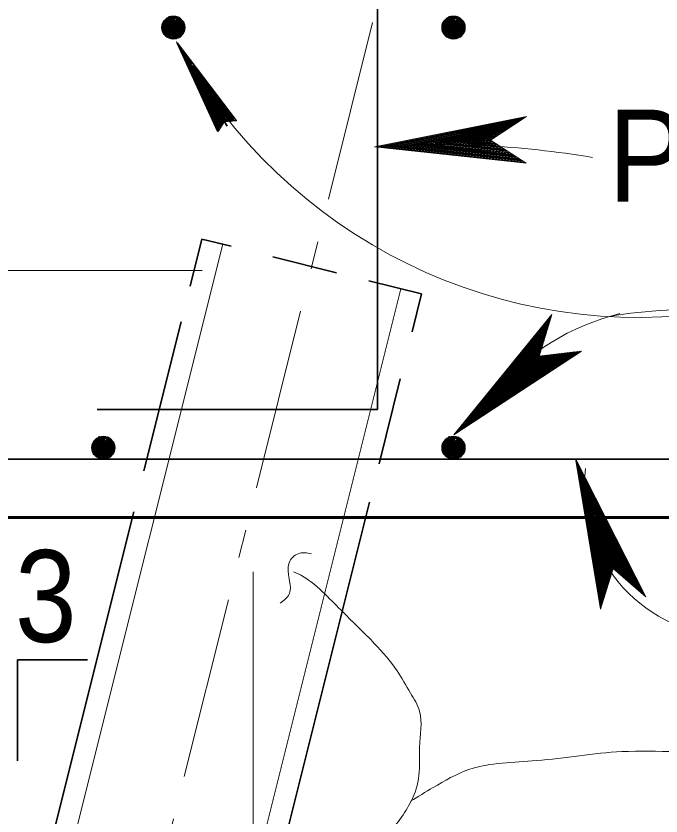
# Model space of a CAD drawing. Extents: x 144 to 252, y 360 to 425.
# Drawn here: x 191.264 to 193.567, y 410.769 to 413.625 of the extents above; entities that cross this region are included whole.
import ezdxf
from ezdxf.enums import TextEntityAlignment as Align

# ---------------------------------------------------------------- set-up
doc = ezdxf.new("R2010")
doc.units = 0
doc.header["$LTSCALE"] = 0.13
doc.linetypes.add('DOT_DASHED', pattern=[7.7, 5, -1.2, 0.3, -1.2])
for name, color, linetype, lineweight in [('1', 7, 'Continuous', 40), ('14', 7, 'Continuous', 13), ('16', 7, 'Continuous', 13), ('3', 7, 'Continuous', 13), ('4', 7, 'Continuous', 35), ('5', 7, 'Continuous', 35)]:
    doc.layers.add(name, color=color, linetype=linetype, lineweight=lineweight)

msp = doc.modelspace()

# ---------------------------------------------------------------- linework, layer by layer
at = {"layer": '1'}
for p, q in [((191.799, 413.6072), (191.7965, 413.5623)), ((191.7965, 413.5922), (191.8565, 413.5822)), ((191.7965, 413.5897), (191.8565, 413.5772)), ((191.8015, 413.6072), (191.799, 413.5623)), ((191.799, 413.6072), (191.859, 413.5972)), ((191.799, 413.6047), (191.859, 413.5947)), ((191.799, 413.6022), (191.859, 413.5897)), ((191.799, 413.5997), (191.859, 413.5872)), ((191.799, 413.5947), (191.8565, 413.5847)), ((191.8015, 413.6122), (191.859, 413.6022)), ((191.804, 413.6072), (191.8015, 413.5623)), ((191.8065, 413.6072), (191.804, 413.5623)), ((191.809, 413.6072), (191.8065, 413.5623)), ((191.814, 413.6072), (191.8115, 413.5623)), ((191.8165, 413.6072), (191.814, 413.5623)), ((191.819, 413.6072), (191.8165, 413.5623)), ((191.8215, 413.6072), (191.819, 413.5623)), ((191.824, 413.6072), (191.8215, 413.5623)), ((191.8265, 413.6072), (191.824, 413.5623)), ((191.829, 413.6072), (191.8265, 413.5623)), ((191.834, 413.6047), (191.829, 413.5598)), ((191.839, 413.6047), (191.834, 413.5598)), ((191.8415, 413.6047), (191.839, 413.5598)), ((191.8415, 413.6047), (191.839, 413.5598)), ((191.844, 413.6047), (191.8415, 413.5598)), ((191.8465, 413.6047), (191.844, 413.5598)), ((191.849, 413.6047), (191.8465, 413.5598)), ((191.8515, 413.6047), (191.849, 413.5598)), ((191.854, 413.6047), (191.8515, 413.5598)), ((191.8565, 413.6047), (191.854, 413.5598)), ((191.8615, 413.6047), (191.859, 413.5598)), ((192.799, 413.6072), (192.7965, 413.5623)), ((192.7965, 413.5922), (192.8565, 413.5822)), ((192.7965, 413.5897), (192.8565, 413.5772)), ((192.8015, 413.6072), (192.799, 413.5623)), ((192.799, 413.6072), (192.859, 413.5972)), ((192.799, 413.6047), (192.859, 413.5947)), ((192.799, 413.6022), (192.859, 413.5897)), ((192.799, 413.5997), (192.859, 413.5872)), ((192.799, 413.5947), (192.8565, 413.5847)), ((192.8015, 413.6122), (192.859, 413.6022)), ((192.804, 413.6072), (192.8015, 413.5623)), ((192.8065, 413.6072), (192.804, 413.5623)), ((192.809, 413.6072), (192.8065, 413.5623)), ((192.814, 413.6072), (192.8115, 413.5623)), ((192.8165, 413.6072), (192.814, 413.5623)), ((192.819, 413.6072), (192.8165, 413.5623)), ((192.8215, 413.6072), (192.819, 413.5623)), ((192.824, 413.6072), (192.8215, 413.5623)), ((192.8265, 413.6072), (192.824, 413.5623)), ((192.829, 413.6072), (192.8265, 413.5623)), ((192.834, 413.6047), (192.829, 413.5598)), ((192.839, 413.6047), (192.834, 413.5598)), ((192.8415, 413.6047), (192.839, 413.5598)), ((192.8415, 413.6047), (192.839, 413.5598)), ((192.844, 413.6047), (192.8415, 413.5598)), ((192.8465, 413.6047), (192.844, 413.5598)), ((192.849, 413.6047), (192.8465, 413.5598)), ((192.8515, 413.6047), (192.849, 413.5598)), ((192.854, 413.6047), (192.8515, 413.5598)), ((192.8565, 413.6047), (192.854, 413.5598)), ((192.8615, 413.6047), (192.859, 413.5598)), ((191.7915, 413.5648), (191.8515, 413.5548)), ((191.794, 413.5797), (191.854, 413.5673)), ((191.794, 413.5722), (191.854, 413.5623)), ((191.794, 413.5697), (191.8515, 413.5598)), ((191.794, 413.5673), (191.8515, 413.5573)), ((191.7965, 413.5872), (191.854, 413.5747)), ((191.7965, 413.5847), (191.854, 413.5722)), ((192.7915, 413.5648), (192.8515, 413.5548)), ((192.794, 413.5797), (192.854, 413.5673)), ((192.794, 413.5722), (192.854, 413.5623)), ((192.794, 413.5697), (192.8515, 413.5598)), ((192.794, 413.5673), (192.8515, 413.5573)), ((192.7965, 413.5872), (192.854, 413.5747)), ((192.7965, 413.5847), (192.854, 413.5722)), ((191.549, 412.1072), (191.5465, 412.0623)), ((191.5515, 412.1072), (191.549, 412.0623)), ((191.549, 412.1072), (191.609, 412.0972)), ((191.549, 412.1047), (191.609, 412.0947)), ((191.5515, 412.1122), (191.609, 412.1022)), ((191.554, 412.1072), (191.5515, 412.0623)), ((191.5565, 412.1072), (191.554, 412.0623)), ((191.559, 412.1072), (191.5565, 412.0623)), ((191.564, 412.1072), (191.5615, 412.0623)), ((191.5665, 412.1072), (191.564, 412.0623)), ((191.569, 412.1072), (191.5665, 412.0623)), ((191.5715, 412.1072), (191.569, 412.0623)), ((191.574, 412.1072), (191.5715, 412.0623)), ((191.5765, 412.1072), (191.574, 412.0623)), ((191.579, 412.1072), (191.5765, 412.0623)), ((191.584, 412.1047), (191.579, 412.0598)), ((191.589, 412.1047), (191.584, 412.0598)), ((191.5915, 412.1047), (191.589, 412.0598)), ((191.5915, 412.1047), (191.589, 412.0598)), ((191.594, 412.1047), (191.5915, 412.0598)), ((191.5965, 412.1047), (191.594, 412.0598)), ((191.599, 412.1047), (191.5965, 412.0598)), ((191.6015, 412.1047), (191.599, 412.0598)), ((191.604, 412.1047), (191.6015, 412.0598)), ((191.6065, 412.1047), (191.604, 412.0598)), ((191.6115, 412.1047), (191.609, 412.0598)), ((192.799, 412.1072), (192.7965, 412.0623)), ((192.8015, 412.1072), (192.799, 412.0623)), ((192.799, 412.1072), (192.859, 412.0972)), ((192.799, 412.1047), (192.859, 412.0947)), ((192.8015, 412.1122), (192.859, 412.1022)), ((192.804, 412.1072), (192.8015, 412.0623)), ((192.8065, 412.1072), (192.804, 412.0623)), ((192.809, 412.1072), (192.8065, 412.0623)), ((192.814, 412.1072), (192.8115, 412.0623)), ((192.8165, 412.1072), (192.814, 412.0623)), ((192.819, 412.1072), (192.8165, 412.0623)), ((192.8215, 412.1072), (192.819, 412.0623)), ((192.824, 412.1072), (192.8215, 412.0623)), ((192.8265, 412.1072), (192.824, 412.0623)), ((192.829, 412.1072), (192.8265, 412.0623)), ((192.834, 412.1047), (192.829, 412.0598)), ((192.839, 412.1047), (192.834, 412.0598)), ((192.8415, 412.1047), (192.839, 412.0598)), ((192.8415, 412.1047), (192.839, 412.0598)), ((192.844, 412.1047), (192.8415, 412.0598)), ((192.8465, 412.1047), (192.844, 412.0598)), ((192.849, 412.1047), (192.8465, 412.0598)), ((192.8515, 412.1047), (192.849, 412.0598)), ((192.854, 412.1047), (192.8515, 412.0598)), ((192.8565, 412.1047), (192.854, 412.0598)), ((192.8615, 412.1047), (192.859, 412.0598)), ((191.544, 412.0797), (191.604, 412.0673)), ((191.5465, 412.0922), (191.6065, 412.0822)), ((191.5465, 412.0897), (191.6065, 412.0772)), ((191.5465, 412.0872), (191.604, 412.0747)), ((191.5465, 412.0847), (191.604, 412.0722)), ((191.549, 412.1022), (191.609, 412.0897)), ((191.549, 412.0997), (191.609, 412.0872)), ((191.549, 412.0947), (191.6065, 412.0847)), ((192.794, 412.0797), (192.854, 412.0673)), ((192.7965, 412.0922), (192.8565, 412.0822)), ((192.7965, 412.0897), (192.8565, 412.0772)), ((192.7965, 412.0872), (192.854, 412.0747)), ((192.7965, 412.0847), (192.854, 412.0722)), ((192.799, 412.1022), (192.859, 412.0897)), ((192.799, 412.0997), (192.859, 412.0872)), ((192.799, 412.0947), (192.8565, 412.0847)), ((191.5415, 412.0648), (191.6015, 412.0548)), ((191.544, 412.0722), (191.604, 412.0623)), ((191.544, 412.0697), (191.6015, 412.0598)), ((191.544, 412.0673), (191.6015, 412.0573)), ((192.7915, 412.0648), (192.8515, 412.0548)), ((192.794, 412.0722), (192.854, 412.0623)), ((192.794, 412.0697), (192.8515, 412.0598)), ((192.794, 412.0673), (192.8515, 412.0573))]:
    msp.add_line(p, q, dxfattribs=at)
at = {"layer": '1', "lineweight": 13}
msp.add_line((191.8372, 413.5337), (191.8387, 413.5312), dxfattribs=at)
at = {"layer": '1', "lineweight": 35}
for p, q in [((192.0178, 413.232), (191.8398, 413.5292)), ((191.9849, 413.2211), (191.8765, 413.4567)), ((191.9862, 413.2212), (191.8775, 413.4572)), ((191.9872, 413.2217), (191.8785, 413.4579)), ((191.9887, 413.2227), (191.8808, 413.4586)), ((191.992, 413.224), (191.8833, 413.4601)), ((192.0397, 413.2532), (191.8935, 413.4465)), ((192.0425, 413.2556), (191.8957, 413.4485)), ((192.0333, 413.2481), (191.8871, 413.4412)), ((192.0366, 413.2507), (191.8902, 413.4438))]:
    msp.add_line(p, q, dxfattribs=at)
at = {"layer": '1', "lineweight": 60}
msp.add_lwpolyline([(190.824, 411.8347), (196.824, 411.8347), (196.824, 413.8347), (194.074, 413.8347), (194.074, 414.0847), (193.574, 414.0847), (193.574, 413.8347), (190.824, 413.8347)], close=True, dxfattribs=at)
at = {"layer": '1'}
for points in [[(191.7865, 413.5822), (191.864, 413.5922), (191.794, 413.6072), (191.864, 413.5747), (191.7915, 413.5623), (191.8515, 413.5522), (191.8515, 413.6147), (191.824, 413.5447), (191.8315, 413.6223), (191.8015, 413.5522), (191.8115, 413.6223), (191.8365, 413.5447), (191.789, 413.5972), (191.8615, 413.6022), (191.8115, 413.5472), (191.844, 413.6198), (191.794, 413.6072), (191.7915, 413.5623), (191.824, 413.5447), (191.8515, 413.5522), (191.864, 413.5747), (191.8615, 413.6022), (191.844, 413.6198), (191.824, 413.5872), (191.859, 413.5598), (191.8015, 413.5522), (191.824, 413.5872), (191.7915, 413.6022), (191.8215, 413.6223), (191.824, 413.5897), (191.849, 413.5522), (191.789, 413.5897), (191.829, 413.5997), (191.8515, 413.6147)], [(192.7865, 413.5822), (192.864, 413.5922), (192.794, 413.6072), (192.864, 413.5747), (192.7915, 413.5623), (192.8515, 413.5522), (192.8515, 413.6147), (192.824, 413.5447), (192.8315, 413.6223), (192.8015, 413.5522), (192.8115, 413.6223), (192.8365, 413.5447), (192.789, 413.5972), (192.8615, 413.6022), (192.8115, 413.5472), (192.844, 413.6198), (192.794, 413.6072), (192.7915, 413.5623), (192.824, 413.5447), (192.8515, 413.5522), (192.864, 413.5747), (192.8615, 413.6022), (192.844, 413.6198), (192.824, 413.5872), (192.859, 413.5598), (192.8015, 413.5522), (192.824, 413.5872), (192.7915, 413.6022), (192.8215, 413.6223), (192.824, 413.5897), (192.849, 413.5522), (192.789, 413.5897), (192.829, 413.5997), (192.8515, 413.6147)], [(191.5365, 412.0822), (191.614, 412.0922), (191.544, 412.1072), (191.614, 412.0747), (191.5415, 412.0623), (191.6015, 412.0522), (191.6015, 412.1147), (191.574, 412.0447), (191.5815, 412.1223), (191.5515, 412.0522), (191.5615, 412.1223), (191.5865, 412.0447), (191.539, 412.0972), (191.6115, 412.1022), (191.5615, 412.0472), (191.594, 412.1198), (191.544, 412.1072), (191.5415, 412.0623), (191.574, 412.0447), (191.6015, 412.0522), (191.614, 412.0747), (191.6115, 412.1022), (191.594, 412.1198), (191.574, 412.0872), (191.609, 412.0598), (191.5515, 412.0522), (191.574, 412.0872), (191.5415, 412.1022), (191.5715, 412.1223), (191.574, 412.0897), (191.599, 412.0522), (191.539, 412.0897), (191.579, 412.0997), (191.6015, 412.1147)], [(192.7865, 412.0822), (192.864, 412.0922), (192.794, 412.1072), (192.864, 412.0747), (192.7915, 412.0623), (192.8515, 412.0522), (192.8515, 412.1147), (192.824, 412.0447), (192.8315, 412.1223), (192.8015, 412.0522), (192.8115, 412.1223), (192.8365, 412.0447), (192.789, 412.0972), (192.8615, 412.1022), (192.8115, 412.0472), (192.844, 412.1198), (192.794, 412.1072), (192.7915, 412.0623), (192.824, 412.0447), (192.8515, 412.0522), (192.864, 412.0747), (192.8615, 412.1022), (192.844, 412.1198), (192.824, 412.0872), (192.859, 412.0598), (192.8015, 412.0522), (192.824, 412.0872), (192.7915, 412.1022), (192.8215, 412.1223), (192.824, 412.0897), (192.849, 412.0522), (192.789, 412.0897), (192.829, 412.0997), (192.8515, 412.1147)]]:
    msp.add_lwpolyline(points, dxfattribs=at)
at = {"layer": '1', "lineweight": 35}
msp.add_lwpolyline([(191.9848, 413.2122), (191.8398, 413.5292), (192.0508, 413.2517), (192.0077, 413.2477)], close=True, dxfattribs=at)
msp.add_lwpolyline([(192.0018, 413.2496), (191.9209, 413.3813), (191.9247, 413.3829), (191.938, 413.3562), (192.0003, 413.2487), (191.9461, 413.3325), (191.9979, 413.2425), (191.9587, 413.3033), (191.9942, 413.2362), (191.9411, 413.3431), (191.8675, 413.4785), (191.891, 413.4552), (191.8658, 413.4904), (192.0088, 413.2537), (191.972, 413.3256), (192.0154, 413.253), (191.9144, 413.3978), (192.0223, 413.2551), (192.0023, 413.2512), (191.989, 413.2256), (191.9893, 413.2353), (191.9977, 413.2485), (191.9901, 413.2534), (191.9835, 413.2427), (192.0072, 413.2507), (192.0238, 413.2526), (192.0415, 413.2549)], dxfattribs=at)
at = {"layer": '1'}
for centre in [(191.8265, 413.5838), (192.8265, 413.5838), (191.5765, 412.0838), (192.8265, 412.0838)]:
    msp.add_circle(centre, 0.0396, dxfattribs=at)
at = {"layer": '1', "lineweight": 13}
msp.add_arc((193.4879, 414.4244), 1.8755, 208.5091, 279.3179, dxfattribs=at)
at = {"layer": '14', "lineweight": 35}
msp.add_lwpolyline([(192.5547, 415.7202), (192.5547, 412.2202), (191.5547, 412.2202)], dxfattribs=at)
at = {"layer": '14'}
for centre, radius, start, end in [((192.7705, 409.8287), 3.3373, 80.4814, 93.8923), ((193.635, 411.7041), 0.8847, 104.0389, 138.6607), ((193.6769, 410.8499), 1.7275, 86.1945, 99.7709), ((193.827, 411.9433), 0.5336, 172.8262, 265.9116)]:
    msp.add_arc(centre, radius, start, end, dxfattribs=at)
at = {"layer": '16', "lineweight": 35}
for p, q in [((191.5203, 411.3269), (191.2703, 411.3269)), ((191.2704, 411.3269), (191.2704, 410.9656))]:
    msp.add_line(p, q, dxfattribs=at)
at = {"layer": '16'}
for points in [[(192.2075, 411.5288), (192.2396, 411.5608), (192.2396, 411.6732), (192.2717, 411.7053), (192.3198, 411.7053)], [(192.5768, 409.9231), (192.4965, 409.9552), (192.4322, 410.0194), (192.4162, 410.0676), (192.4002, 410.1478), (192.4002, 410.18), (192.4002, 410.2442), (192.4483, 410.3566), (192.4483, 410.3887), (192.4965, 410.5653), (192.5286, 410.6456), (192.6089, 410.7259), (192.6571, 410.7901), (192.6892, 410.8543), (192.7053, 410.9507), (192.7053, 411.0149), (192.7053, 411.1433), (192.6731, 411.2076), (192.6249, 411.2878), (192.5447, 411.3842), (192.4322, 411.4966), (192.368, 411.5608), (192.2877, 411.6251), (192.2557, 411.6411)], [(192.6731, 410.8222), (192.7534, 410.8704), (192.8818, 410.9347), (193.1227, 410.9667), (193.4278, 410.9988), (193.6204, 410.9988), (193.9094, 410.9988), (194.1502, 410.9988), (194.359, 411.0149), (194.5035, 411.0149), (194.6641, 411.047), (194.8086, 411.0792), (195.0012, 411.1273), (195.21, 411.2397), (195.2742, 411.2878), (195.3224, 411.336), (195.3866, 411.3842), (195.4508, 411.4163)]]:
    msp.add_spline(points, degree=3, dxfattribs=at)
at = {"layer": '3'}
for p, q in [((193.0875, 413.2665), (192.5439, 413.1583)), ((193.0817, 413.2627), (192.5583, 413.1584)), ((193.0783, 413.2604), (192.5692, 413.159)), ((193.0738, 413.2575), (192.5836, 413.1598)), ((193.0699, 413.2549), (192.5962, 413.1605)), ((193.0699, 413.2549), (192.5962, 413.1605)), ((193.0664, 413.2525), (192.6076, 413.1612)), ((193.062, 413.2496), (192.622, 413.1619)), ((193.058, 413.247), (192.6347, 413.1627)), ((192.9584, 413.1812), (193.0875, 413.2665)), ((193.0537, 413.2442), (192.6484, 413.1634)), ((193.0495, 413.2414), (192.6623, 413.1642)), ((193.0454, 413.2387), (192.6755, 413.1649)), ((193.041, 413.2357), (192.6894, 413.1657)), ((193.0372, 413.2332), (192.7019, 413.1664)), ((193.0336, 413.2308), (192.7133, 413.1671)), ((193.0288, 413.2278), (192.729, 413.1679)), ((193.0244, 413.2248), (192.7428, 413.1687)), ((193.0175, 413.2202), (192.7608, 413.1692)), ((193.0206, 413.2223), (192.7623, 413.1708)), ((193.0132, 413.2174), (192.7747, 413.17)), ((193.0092, 413.2147), (192.7878, 413.1707)), ((193.0077, 413.2138), (192.7969, 413.1717)), ((193.0039, 413.2113), (192.8088, 413.1724)), ((192.9997, 413.2084), (192.8227, 413.1732)), ((192.9948, 413.2053), (192.8383, 413.174)), ((192.9909, 413.2027), (192.8509, 413.1747)), ((192.9868, 413.1999), (192.8641, 413.1755)), ((192.9831, 413.1975), (192.8761, 413.1762)), ((192.9786, 413.1945), (192.8906, 413.1769)), ((192.9743, 413.1918), (192.9044, 413.1778)), ((192.9703, 413.1892), (192.917, 413.1784)), ((192.9587, 413.1814), (192.5439, 413.1583)), ((192.5962, 413.1605), (193.0707, 413.1087)), ((192.6076, 413.1612), (193.0672, 413.111)), ((192.622, 413.1619), (193.0627, 413.1139)), ((192.6347, 413.1627), (193.0589, 413.1165)), ((192.6484, 413.1634), (193.0547, 413.1192)), ((192.6623, 413.1642), (193.0504, 413.1219)), ((192.6755, 413.1649), (193.0463, 413.1245)), ((192.6894, 413.1657), (193.0421, 413.1273)), ((192.7019, 413.1664), (193.0382, 413.1298)), ((192.7133, 413.1671), (193.0347, 413.1321)), ((192.729, 413.1679), (193.0299, 413.1352)), ((192.7428, 413.1687), (193.0257, 413.1379)), ((192.7608, 413.1692), (193.0212, 413.1407)), ((192.7747, 413.17), (193.0169, 413.1435)), ((192.7878, 413.1707), (193.0129, 413.1462)), ((192.7969, 413.1717), (193.009, 413.1487)), ((192.8088, 413.1724), (193.0052, 413.1511)), ((192.8227, 413.1732), (193.0011, 413.1538)), ((192.8383, 413.174), (192.9962, 413.1568)), ((192.8509, 413.1747), (192.9924, 413.1593)), ((192.8641, 413.1755), (192.9883, 413.1619)), ((192.8761, 413.1762), (192.9846, 413.1644)), ((192.8906, 413.1769), (192.9802, 413.1672)), ((192.9044, 413.1778), (192.9758, 413.1699)), ((192.917, 413.1784), (192.972, 413.1725)), ((192.9303, 413.1792), (192.968, 413.1751)), ((192.9652, 413.1857), (192.9404, 413.1808)), ((192.9627, 413.1841), (192.9417, 413.1798)), ((192.9417, 413.1798), (192.9644, 413.1773)), ((192.9518, 413.1803), (192.9613, 413.1794)), ((193.0857, 413.0991), (192.9584, 413.1812)), ((192.5439, 413.1583), (193.0857, 413.0991)), ((192.5583, 413.1584), (193.0823, 413.1012)), ((192.5692, 413.159), (193.079, 413.1034)), ((192.5836, 413.1598), (193.0746, 413.1063)), ((191.9288, 412.7168), (188.8299, 412.7168)), ((193.178, 412.5589), (192.8271, 412.1299)), ((193.1759, 412.5523), (192.8382, 412.1392)), ((193.1747, 412.5484), (192.8461, 412.1465)), ((193.1732, 412.5434), (192.8568, 412.1563)), ((193.1718, 412.5389), (192.8661, 412.165)), ((193.1718, 412.5389), (192.8661, 412.165)), ((193.1705, 412.5348), (192.8744, 412.1727)), ((193.1325, 412.4111), (193.178, 412.5589)), ((193.1689, 412.5297), (192.885, 412.1824)), ((193.1677, 412.5252), (192.8944, 412.191)), ((193.1661, 412.5203), (192.9045, 412.2003)), ((193.1645, 412.5155), (192.9146, 412.2097)), ((193.1631, 412.5107), (192.9244, 412.2188)), ((193.1616, 412.5057), (192.9347, 412.2281)), ((193.1602, 412.5013), (192.9439, 412.2367)), ((193.1589, 412.4972), (192.9523, 412.2444)), ((193.1572, 412.4917), (192.9639, 412.255)), ((193.1558, 412.4867), (192.974, 412.2644)), ((193.1533, 412.4787), (192.9875, 412.2763)), ((193.1543, 412.4823), (192.9877, 412.2785)), ((193.1518, 412.4739), (192.9978, 412.2857)), ((193.1503, 412.4692), (193.0075, 412.2946)), ((193.1499, 412.4675), (193.0138, 412.3012)), ((193.1484, 412.4633), (193.0227, 412.3092)), ((193.1471, 412.4583), (193.0328, 412.3186)), ((193.1453, 412.4528), (193.0443, 412.3293)), ((193.1439, 412.4482), (193.0536, 412.3378)), ((192.8271, 412.1299), (193.283, 412.4286)), ((192.8382, 412.1392), (193.279, 412.4281)), ((192.8461, 412.1465), (193.275, 412.4277)), ((192.8568, 412.1563), (193.2697, 412.4271)), ((192.8661, 412.165), (193.2652, 412.4266)), ((192.8744, 412.1727), (193.2611, 412.426)), ((192.885, 412.1824), (193.2558, 412.4255)), ((192.8944, 412.191), (193.2512, 412.4249)), ((192.9045, 412.2003), (193.2463, 412.4243)), ((192.9146, 412.2097), (193.2412, 412.4237)), ((192.9244, 412.2188), (193.2364, 412.4232)), ((192.9347, 412.2281), (193.2313, 412.4227)), ((192.9439, 412.2367), (193.2268, 412.4221)), ((192.9523, 412.2444), (193.2226, 412.4216)), ((192.9639, 412.255), (193.217, 412.4209)), ((192.974, 412.2644), (193.2119, 412.4204)), ((192.9875, 412.2763), (193.2067, 412.4197)), ((192.9978, 412.2857), (193.2016, 412.4192)), ((193.0075, 412.2946), (193.1968, 412.4187)), ((193.0138, 412.3012), (193.1923, 412.4181)), ((193.0227, 412.3092), (193.1878, 412.4176)), ((193.1425, 412.4435), (193.0634, 412.3467)), ((193.1412, 412.4393), (193.0722, 412.3548)), ((193.1396, 412.4342), (193.0829, 412.3647)), ((193.1381, 412.4292), (193.093, 412.374)), ((193.1367, 412.4248), (193.1023, 412.3826)), ((193.135, 412.419), (193.1189, 412.3994)), ((193.283, 412.4286), (193.1325, 412.4111)), ((193.1326, 412.4114), (192.8271, 412.1299)), ((193.0328, 412.3186), (193.1828, 412.417)), ((193.0443, 412.3293), (193.1772, 412.4162)), ((193.0536, 412.3378), (193.1727, 412.4158)), ((193.0634, 412.3467), (193.1678, 412.4153)), ((193.0722, 412.3548), (193.1633, 412.4147)), ((193.0829, 412.3647), (193.1582, 412.414)), ((193.093, 412.374), (193.1531, 412.4135)), ((193.1023, 412.3826), (193.1486, 412.413)), ((193.1121, 412.3916), (193.1438, 412.4124)), ((193.134, 412.416), (193.1205, 412.3993)), ((193.1205, 412.3993), (193.1397, 412.4119)), ((193.128, 412.4062), (193.1359, 412.4115)), ((193.2618, 412.0454), (193.3512, 411.5079)), ((193.3962, 411.6524), (193.2618, 412.0454)), ((193.5128, 411.5514), (193.2618, 412.0454)), ((193.2657, 412.0316), (193.3525, 411.5116)), ((193.5077, 411.5558), (193.2657, 412.0316)), ((193.2693, 412.0213), (193.3537, 411.5155)), ((193.5047, 411.5586), (193.2693, 412.0213)), ((193.2739, 412.0077), (193.3552, 411.5205)), ((193.5007, 411.5621), (193.2739, 412.0077)), ((193.2781, 411.9956), (193.3565, 411.5249)), ((193.4971, 411.5651), (193.2781, 411.9956)), ((193.4971, 411.5651), (193.2781, 411.9956)), ((193.2817, 411.985), (193.3577, 411.5289)), ((193.4938, 411.5679), (193.2817, 411.985)), ((193.2863, 411.9712), (193.3594, 411.5339)), ((193.4897, 411.5713), (193.2863, 411.9712)), ((193.2906, 411.9592), (193.3608, 411.5384)), ((193.4862, 411.5745), (193.2906, 411.9592)), ((193.2951, 411.9462), (193.3622, 411.5433)), ((193.4824, 411.5779), (193.2951, 411.9462)), ((193.2995, 411.9331), (193.3637, 411.548)), ((193.4784, 411.5812), (193.2995, 411.9331)), ((193.3037, 411.9205), (193.3652, 411.5526)), ((193.4747, 411.5844), (193.3037, 411.9205)), ((193.3082, 411.9073), (193.3667, 411.5574)), ((193.4707, 411.5877), (193.3082, 411.9073)), ((193.3123, 411.8954), (193.368, 411.5617)), ((193.4673, 411.5908), (193.3123, 411.8954)), ((193.316, 411.8847), (193.3692, 411.5659)), ((193.464, 411.5936), (193.316, 411.8847)), ((193.3212, 411.8698), (193.371, 411.5714)), ((193.4598, 411.5975), (193.3212, 411.8698)), ((193.3256, 411.8567), (193.3723, 411.5762)), ((193.4557, 411.6008), (193.3256, 411.8567)), ((193.3309, 411.8396), (193.3741, 411.5812)), ((193.4496, 411.6062), (193.3309, 411.8396)), ((193.4523, 411.6038), (193.333, 411.8386)), ((193.3354, 411.8264), (193.3754, 411.5861)), ((193.4457, 411.6096), (193.3354, 411.8264)), ((193.3397, 411.814), (193.3768, 411.5907)), ((193.4418, 411.6128), (193.3397, 411.814)), ((193.3431, 411.8055), (193.3782, 411.5951)), ((193.4407, 411.6139), (193.3431, 411.8055)), ((193.347, 411.7942), (193.3795, 411.5993)), ((193.4372, 411.6169), (193.347, 411.7942)), ((193.3514, 411.781), (193.3812, 411.6042)), ((193.4332, 411.6203), (193.3514, 411.781)), ((193.3565, 411.7663), (193.3826, 411.6096)), ((193.429, 411.624), (193.3565, 411.7663)), ((193.3607, 411.7544), (193.3841, 411.6139)), ((193.4253, 411.6271), (193.3607, 411.7544)), ((193.3649, 411.7418), (193.3855, 411.6186)), ((193.4217, 411.6303), (193.3649, 411.7418)), ((193.3688, 411.7305), (193.3868, 411.6229)), ((193.4183, 411.6332), (193.3688, 411.7305)), ((193.3735, 411.7167), (193.3882, 411.6278)), ((193.4142, 411.6367), (193.3735, 411.7167)), ((193.378, 411.7037), (193.3897, 411.6327)), ((193.4103, 411.6401), (193.378, 411.7037)), ((193.3821, 411.6917), (193.3912, 411.6371)), ((193.4068, 411.6432), (193.3821, 411.6917)), ((193.3864, 411.6792), (193.3927, 411.6417)), ((193.3512, 411.5079), (193.396, 411.6526)), ((193.3901, 411.6683), (193.3938, 411.6457)), ((193.3998, 411.6492), (193.3901, 411.6683)), ((193.4022, 411.6472), (193.3907, 411.6697)), ((193.3932, 411.6587), (193.395, 411.6493)), ((193.396, 411.6526), (193.5128, 411.5514)), ((192.1112, 408.3071), (192.1112, 411.6411))]:
    msp.add_line(p, q, dxfattribs=at)
at = {"layer": '4'}
msp.add_line((191.074, 412.0431), (196.574, 412.0431), dxfattribs=at)
at = {"layer": '5', "linetype": 'DOT_DASHED', "lineweight": 13}
msp.add_line((192.5378, 413.6012), (191.4277, 409.1598), dxfattribs=at)
at = {"layer": '5'}
for p, q in [((191.9282, 412.8288), (191.886, 412.6601)), ((191.9282, 412.8288), (192.0326, 412.8027)), ((192.1809, 412.7656), (192.4092, 412.7085)), ((192.5238, 412.6798), (192.7123, 412.6327)), ((192.7123, 412.6327), (192.6786, 412.4977)), ((191.8543, 412.5329), (191.7213, 412.0012)), ((192.6364, 412.3292), (192.5608, 412.0267)), ((192.5264, 411.889), (191.9848, 409.7222)), ((191.6847, 411.8548), (191.2007, 409.9183))]:
    msp.add_line(p, q, dxfattribs=at)
at = {"layer": '5', "lineweight": 13}
for p, q in [((192.0025, 412.8102), (191.275, 409.8997)), ((192.638, 412.6513), (191.9105, 409.7408))]:
    msp.add_line(p, q, dxfattribs=at)

# ---------------------------------------------------------------- texts
at = {"layer": '14', "width": 0.95}
msp.add_text('P505', height=0.3281, dxfattribs=at).set_placement((193.8647, 412.9623), align=Align.CENTER)
at = {"layer": '16', "width": 0.9}
msp.add_text('3', height=0.3281, dxfattribs=at).set_placement((191.3708, 411.39), align=Align.CENTER)

doc.saveas('drawing.dxf')
